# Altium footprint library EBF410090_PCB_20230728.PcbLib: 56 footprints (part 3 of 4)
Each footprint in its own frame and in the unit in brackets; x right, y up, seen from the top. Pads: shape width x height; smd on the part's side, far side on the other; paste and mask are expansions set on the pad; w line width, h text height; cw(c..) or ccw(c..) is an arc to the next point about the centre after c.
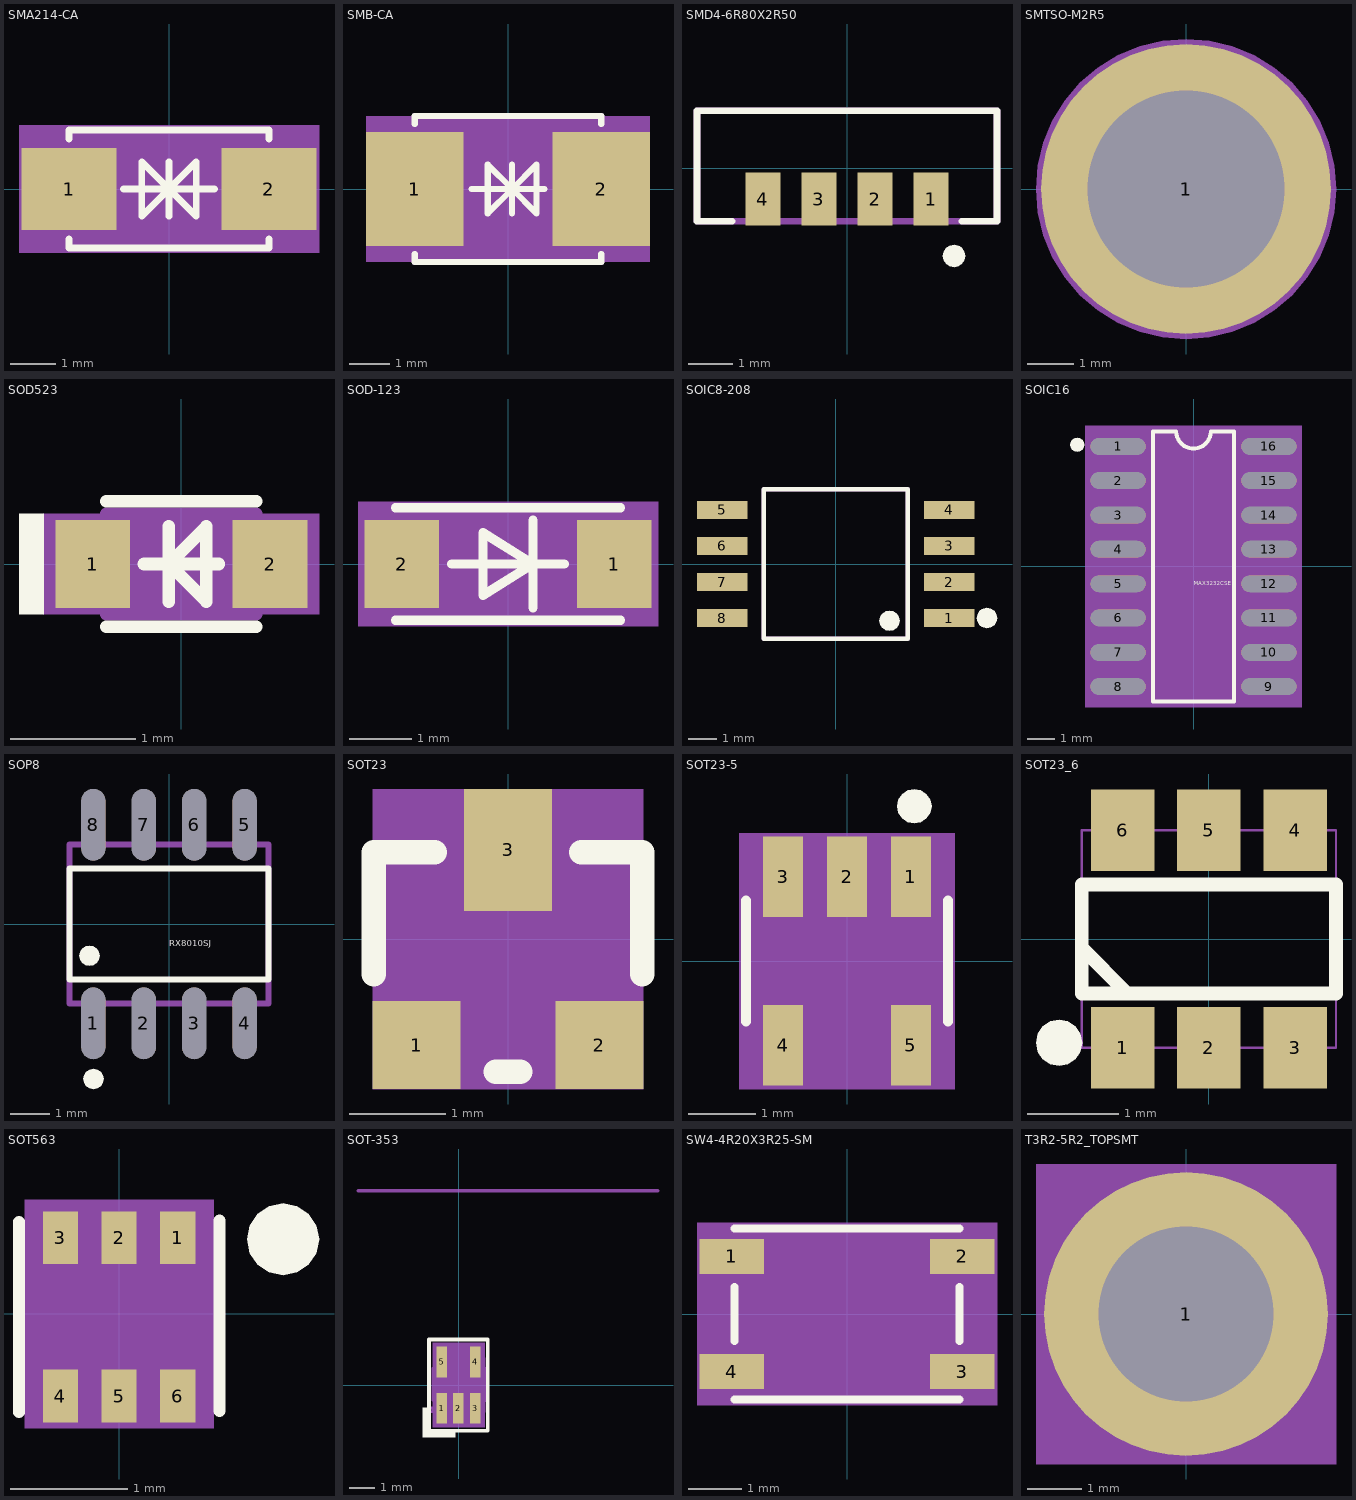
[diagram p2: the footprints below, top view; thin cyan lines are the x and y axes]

## SMA214-CA [mm] "SMA214-CA"
pads (2):
  rect 2.1x1.8 smd: 1(-2.2,0) 2(2.2,0)
Top Overlay:
  lines w0.15: -2.2,-1.1 -2.2,-1.3 2.2,-1.3 2.2,-1.1 ; -2.2,1.1 -2.2,1.3 2.2,1.3 2.2,1.1 ; -1,0 1,0 ; 0,-0.6 0,0.6 ; 0,0 0.6,-0.6 0.6,0.6 0,0 ; 0,0 -0.6,0.6 -0.6,-0.6 0,0
Top 3D Body:
  region: -3.3,1.4 -3.3,-1.4 3.3,-1.4 3.3,1.4
Mechanical 16:
  text "2" at 1.946,0 h0.64
  text "1" at -2.454,0 h0.64
Top Assembly:
  lines w0.15: -2.2,-1.25 -2.2,1.25 2.2,1.25 2.2,-1.25 -2.2,-1.25
3D body: height 3.81, standoff 0, extent -3.3,-1.4 3.3,1.4

## SMB-CA [mm] "SMB-CA"
pads (2):
  rect 2.4x2.8 smd: 1(-2.3,0) 2(2.3,0)
Top Overlay:
  lines w0.15: -2.3,-1.6 -2.3,-1.8 2.3,-1.8 2.3,-1.6 ; -2.3,1.6 -2.3,1.8 2.3,1.8 2.3,1.6 ; -0.9,0 0.9,0 ; 0.1,0 -0.5,0.6 -0.5,-0.6 0.1,0 ; 0.1,0 0.7,-0.6 0.7,0.6 0.1,0 ; 0.1,-0.6 0.1,0.6 0.1,-0.6
Top 3D Body:
  region: -3.5,1.8 -3.5,-1.8 3.5,-1.8 3.5,1.8
Mechanical 16:
  text "2" at 2.3,0.254 h0.64
  text "1" at -2.3,0.254 h0.64
Top Assembly:
  lines w0.15: -2.3,-1.8 -2.3,1.8 2.3,1.8 2.3,-1.8 -2.3,-1.8
3D body: height 3.81, standoff 0, extent -3.5,-1.8 3.5,1.8

## SMD4-6R80X2R50 [mil] "SMD4-6R80X2R50"
pads (4):
  rect 31.5x47.24 smd: 1(75,-27.56) 2(25,-27.56) 3(-25,-27.56) 4(-75,-27.56)
Top Overlay:
  dashed: 85.48,-78.3 86.24,-82.14 88.42,-85.39 91.67,-87.57 95.51,-88.33 99.35,-87.57 100.44,-86.84 102.6,-85.39 104.78,-82.14 105.54,-78.3 104.78,-74.46 102.6,-71.21 100.44,-69.76 99.35,-69.03 95.51,-68.27 91.67,-69.03 88.42,-71.21 86.24,-74.46
  lines w5.91: -102.36,-47.25 -133.86,-47.25 -133.86,51.18 133.86,51.18 133.86,-47.25 102.36,-47.25
Top Assembly:
  lines w5.91: -133.86,-47.25 -133.86,51.18 133.86,51.18 133.86,-47.25 -133.86,-47.25

## SMTSO-M2R5 [mm] "SMTSO-M2R5"
pads (1):
  round 6.2 / inner round 5.2 / far side round 5.2 hole 4.22: 1(0,0)
Top Overlay:
  text "M2.5X3mm" at -0.488,-0.076 h0.15
Top Paste:
  dashed: 3.074,0.4 2.072,0.4 2.029,0.579 1.971,0.754 1.898,0.923 1.81,1.085 1.709,1.238 1.594,1.382 1.468,1.516 1.33,1.638 1.182,1.748 1.025,1.844 0.861,1.927 0.689,1.994 0.513,2.047 0.4,2.072 0.4,3.074 0.666,3.028 0.928,2.958 1.182,2.866 1.427,2.752 1.662,2.617 1.884,2.462 2.091,2.289 2.282,2.098 2.457,1.891 2.612,1.67 2.748,1.436 2.862,1.191 2.955,0.937 3.026,0.675 3.073,0.409
  dashed: 0.4,-3.074 0.4,-2.072 0.579,-2.029 0.754,-1.971 0.923,-1.898 1.085,-1.81 1.238,-1.709 1.382,-1.594 1.516,-1.468 1.638,-1.33 1.748,-1.182 1.844,-1.025 1.927,-0.861 1.994,-0.689 2.047,-0.513 2.072,-0.4 3.074,-0.4 3.028,-0.666 2.958,-0.928 2.866,-1.182 2.752,-1.427 2.617,-1.662 2.462,-1.884 2.289,-2.091 2.098,-2.282 1.891,-2.457 1.67,-2.612 1.436,-2.748 1.191,-2.862 0.937,-2.955 0.675,-3.026 0.409,-3.073
  dashed: -3.074,-0.4 -2.072,-0.4 -2.029,-0.579 -1.971,-0.754 -1.898,-0.923 -1.81,-1.085 -1.709,-1.238 -1.594,-1.382 -1.468,-1.516 -1.33,-1.638 -1.182,-1.748 -1.025,-1.844 -0.861,-1.927 -0.689,-1.994 -0.513,-2.047 -0.4,-2.072 -0.4,-3.074 -0.666,-3.028 -0.928,-2.958 -1.182,-2.866 -1.427,-2.752 -1.662,-2.617 -1.884,-2.462 -2.091,-2.289 -2.282,-2.098 -2.457,-1.891 -2.612,-1.67 -2.748,-1.436 -2.862,-1.191 -2.955,-0.937 -3.026,-0.675 -3.073,-0.409
  dashed: -0.4,3.074 -0.4,2.072 -0.579,2.029 -0.754,1.971 -0.923,1.898 -1.085,1.81 -1.238,1.709 -1.382,1.594 -1.516,1.468 -1.638,1.33 -1.748,1.182 -1.844,1.025 -1.927,0.861 -1.994,0.689 -2.047,0.513 -2.072,0.4 -3.074,0.4 -3.028,0.666 -2.958,0.928 -2.866,1.182 -2.752,1.427 -2.617,1.662 -2.462,1.884 -2.289,2.091 -2.098,2.282 -1.891,2.457 -1.67,2.612 -1.436,2.748 -1.191,2.862 -0.937,2.955 -0.675,3.026 -0.409,3.073
Top 3D Body:
  region: 3.21,0 3.17,0.502 3.053,0.992 2.86,1.457 2.597,1.887 2.27,2.27 1.887,2.597 1.457,2.86 0.992,3.053 0.502,3.17 0,3.21 -0.502,3.17 -0.992,3.053 -1.457,2.86 -1.6,2.772 -1.887,2.597 -2.27,2.27 -2.597,1.887 -2.86,1.457 -3.053,0.992 -3.17,0.502 -3.21,0 -3.17,-0.502 -3.053,-0.992 -2.86,-1.457 -2.597,-1.887 -2.27,-2.27 -1.887,-2.597 -1.6,-2.772 -1.457,-2.86 -0.992,-3.053 -0.502,-3.17 0,-3.21 0.502,-3.17 0.992,-3.053 1.457,-2.86 1.887,-2.597 2.27,-2.27 2.597,-1.887 2.86,-1.457 3.053,-0.992 3.17,-0.502
Mechanical 16:
  text "1" at -0.254,0 h0.64
Top Assembly:
  circle w0.025: c0,0 r3.1
3D body: height 3.81, standoff 0, extent -3.21,-3.21 3.21,3.21

## SOD523 [mm] "SOD523"
pads (2):
  rect 0.6x0.7 smd: 1(-0.71,0) 2(0.71,0)
Top Overlay:
  dashed: -1.3,0.4 -1.3,-0.4 -1.1,-0.4 -1.1,0.4
  lines w0.1: -0.6,-0.5 0.6,-0.5 ; -0.6,0.5 0.6,0.5 ; -0.3,0 0.3,0 ; -0.1,-0.3 -0.1,0.3 ; -0.1,0 0.2,-0.3 0.2,0.3 -0.1,0
Top 3D Body:
  region: -1.1,0.4 -1.1,-0.4 1.1,-0.4 1.1,0.4
Top Assembly:
  lines w0.1: -0.6,-0.4 -0.6,0.4 0.6,0.4 0.6,-0.4 -0.6,-0.4
3D body: height 3.81, standoff 0, extent -1.1,-0.4 1.1,0.4

## SOD-123 [mm] "SOD-123"
pads (2):
  rect 1.2x1.4 smd: 1(1.7,0) 2(-1.7,0)
Top Overlay:
  lines w0.15: -1.8,-0.9 1.8,-0.9 ; -1.8,0.9 1.8,0.9 ; -0.9,0 0.9,0 ; 0.4,-0.7 0.4,0.7 ; -0.4,-0.5 0.4,0 -0.4,0.5 -0.4,-0.5
  text "1N5819W" at 1.199,-0.076 h0.15
Top 3D Body:
  region: -2.4,-1 2.4,-1 2.4,1 -2.4,1
Mechanical 16:
  text "2" at -2.015,0 h0.79
  text "1" at 1.385,0 h0.79
Top Assembly:
  lines w0.15: -1.8,-0.9 -1.8,0.9 1.8,0.9 1.8,-0.9 -1.8,-0.9
3D body: height 3.81, standoff 0, extent -2.4,-1 2.4,1

## SOIC8-208 [mm] "SOIC8-208"
pads (8):
  rect 1.778x0.635 smd: 1(4,-1.905) 2(4,-0.635) 3(4,0.635) 4(4,1.905) 5(-4,1.905) 6(-4,0.635) 7(-4,-0.635) 8(-4,-1.905)
Top Overlay:
  dashed: 2.257,-2 2.23,-2.137 2.152,-2.253 2.037,-2.33 1.9,-2.357 1.763,-2.33 1.724,-2.304 1.647,-2.253 1.57,-2.137 1.543,-2 1.57,-1.863 1.647,-1.747 1.724,-1.696 1.763,-1.67 1.9,-1.643 2.037,-1.67 2.152,-1.747 2.23,-1.863
  dashed: 5.691,-1.905 5.664,-2.042 5.586,-2.157 5.471,-2.235 5.334,-2.262 5.197,-2.235 5.159,-2.209 5.082,-2.157 5.004,-2.042 4.977,-1.905 5.004,-1.768 5.082,-1.653 5.159,-1.601 5.197,-1.575 5.334,-1.548 5.471,-1.575 5.586,-1.653 5.664,-1.768
  lines w0.152: -2.54,-2.64 2.54,-2.64 2.54,2.64 -2.54,2.64 -2.54,-2.64
Top Assembly:
  lines w0.152: -2.54,-2.64 2.54,-2.64 2.54,2.64 -2.54,2.64 -2.54,-2.64

## SOIC16 [mil] "SOIC16"
pads (16):
  oval 80x24 smd: 1(-109.8,174.8) 2(-109.8,125.2) 3(-109.8,74.8) 4(-109.8,25.2) 5(-109.8,-25.2) 6(-109.8,-74.8) 7(-109.8,-125.2) 8(-109.8,-174.8) 9(109.8,-174.8) 10(109.8,-125.2) 11(109.8,-74.8) 12(109.8,-25.2) 13(109.8,25.2) 14(109.8,74.8) 15(109.8,125.2) 16(109.8,174.8)
Top Overlay:
  dashed: -169.29,187.2 -165.45,186.44 -162.2,184.26 -160.02,181.01 -159.26,177.17 -160.02,173.33 -160.75,172.24 -162.2,170.08 -165.45,167.9 -169.29,167.14 -173.13,167.9 -176.38,170.08 -177.83,172.24 -178.56,173.33 -179.32,177.17 -178.56,181.01 -176.38,184.26 -173.13,186.44
  lines w5.91: -59.06,-196.85 59.06,-196.85 59.06,196.85 25.2,196.85 cw(c0,196.85) -25.2,196.85 -39.37,196.85 -59.06,196.85 -59.06,-196.85
  text "MAX3232CSE" at 0.01,-27 h6
Top 3D Body:
  region: -157.48,204.72 -157.48,-204.72 157.48,-204.72 157.48,204.72
Mechanical 16:
  text "8" at -109.8,-179.52 h11.8
  text "13" at 109.8,15.76 h11.8
  text "14" at 109.8,65.36 h11.8
  text "7" at -109.8,-129.92 h11.8
  text "15" at 109.8,115.76 h11.8
  text "16" at 109.8,165.36 h11.8
  text "1" at -109.8,170.08 h11.8
  text "3" at -109.8,70.08 h11.8
  text "12" at 109.8,-34.64 h11.8
  text "9" at 109.8,-179.52 h11.8
  text "10" at 109.8,-134.64 h11.8
  text "4" at -109.8,20.48 h11.8
  text "11" at 109.8,-84.24 h11.8
  text "5" at -109.8,-29.92 h11.8
  text "6" at -109.8,-79.52 h11.8
  text "2" at -109.8,120.48 h11.8
3D body: height 150, standoff 0, extent -157.48,-204.72 157.48,204.72

## SOP8 [mm] "SOP8"
pads (8):
  oval 0.6x1.8 smd: 1(-1.905,-2.5) 2(-0.635,-2.5) 3(0.635,-2.5) 4(1.905,-2.5) 5(1.905,2.5) 6(0.635,2.5) 7(-0.635,2.5) 8(-1.905,2.5)
Top Overlay:
  dashed: -2,-0.545 -1.902,-0.565 -1.82,-0.62 -1.765,-0.703 -1.745,-0.8 -1.765,-0.898 -1.783,-0.925 -1.82,-0.98 -1.902,-1.036 -2,-1.055 -2.098,-1.036 -2.18,-0.98 -2.217,-0.925 -2.235,-0.898 -2.255,-0.8 -2.235,-0.703 -2.18,-0.62 -2.098,-0.565
  dashed: -1.9,-3.645 -1.802,-3.664 -1.72,-3.72 -1.664,-3.802 -1.645,-3.9 -1.664,-3.997 -1.683,-4.025 -1.72,-4.08 -1.802,-4.135 -1.9,-4.155 -1.997,-4.135 -2.08,-4.08 -2.117,-4.025 -2.135,-3.997 -2.155,-3.9 -2.135,-3.802 -2.08,-3.72 -1.997,-3.664
  lines w0.15: -2.5,-1.4 -2.5,1.4 2.5,1.4 2.5,-1.4 -2.5,-1.4
  text "RX8010SJ" at 0,-0.564 h0.15
Mechanical 16:
  text "1" at -1.905,-2.754 h0.64
Top Assembly:
  lines w0.15: -2.5,-2 -2.5,2 2.5,2 2.5,-2 -2.5,-2

## SOT23 [mil] "SOT23"
pads (3):
  rect 36x36 smd: 1(-37.5,-43.5) 2(37.5,-43.5)
  rect 36x50 smd: 3(0,36.5)
Top Overlay:
  lines w10: -55,-14.5 -55,35.5 -30,35.5 ; -5,-54.5 5,-54.5 ; 30,35.5 55,35.5 55,-14.5
Top 3D Body:
  region: -55.5,-61.5 -55.5,61.5 55.5,61.5 55.5,-61.5
3D body: height 150, standoff 0, extent -55.5,-61.5 55.5,61.5

## SOT23-5 [mm] "SOT23-5"
pads (5):
  rect 0.599x1.199 smd: 1(0.95,1.25) 2(0,1.25) 3(-0.95,1.25) 4(-0.95,-1.25) 5(0.95,-1.25)
Top Overlay:
  dashed: 1.255,2.3 1.235,2.202 1.18,2.12 1.098,2.065 1,2.045 0.902,2.065 0.875,2.083 0.82,2.12 0.765,2.202 0.745,2.3 0.765,2.397 0.82,2.48 0.875,2.517 0.902,2.535 1,2.555 1.098,2.535 1.18,2.48 1.235,2.397
  lines w0.15: -1.5,-0.9 -1.5,0.9 ; 1.5,-0.9 1.5,0.9
Top 3D Body:
  region: 1.6,-1.9 1.6,1.9 -1.6,1.9 -1.6,-1.9
Mechanical 16:
  text "5" at 0.91,-1.25 h0.1
  text "3" at -0.99,1.25 h0.1
  text "4" at -0.99,-1.25 h0.1
  text "1" at 0.91,1.25 h0.1
  text "2" at -0.04,1.25 h0.1
Top Assembly:
  lines w0.15: -1.5,-0.85 1.5,-0.85 1.5,0.85 -1.5,0.85 -1.5,-0.85
3D body: height 3.81, standoff 0, extent -1.6,-1.9 1.6,1.9

## SOT23_6 [mm] "SOT23_6"
pads (6):
  rect 0.7x0.9 smd: 1(-0.95,-1.2) 2(0,-1.2) 3(0.95,-1.2) 4(0.95,1.2) 5(0,1.2) 6(-0.95,1.2)
Top Overlay:
  dashed: -1.651,-0.888 -1.553,-0.908 -1.471,-0.963 -1.416,-1.045 -1.396,-1.143 -1.416,-1.241 -1.434,-1.268 -1.471,-1.323 -1.553,-1.378 -1.651,-1.398 -1.749,-1.378 -1.831,-1.323 -1.868,-1.268 -1.886,-1.241 -1.906,-1.143 -1.886,-1.045 -1.831,-0.963 -1.749,-0.908
  lines w0.15: -1.4,-0.1 -0.9,-0.6 ; -1.4,-0.6 1.4,-0.6 1.4,0.6 -1.4,0.6 -1.4,-0.6
Top 3D Body:
  lines w0.025: -1.4,-1.2 1.4,-1.2 1.4,1.2 -1.4,1.2 -1.4,-1.2
Mechanical 16:
  text "3" at 0.95,-1.454 h0.64
  text "5" at 0,0.946 h0.64
  text "4" at 0.95,0.946 h0.64
  text "6" at -0.95,0.946 h0.64
  text "2" at 0,-1.454 h0.64
  text "1" at -0.95,-1.454 h0.64
Top Assembly:
  lines w0.025: -1.4,-1.2 1.4,-1.2 1.4,1.2 -1.4,1.2 -1.4,-1.2

## SOT563 [mm] "SOT563"
pads (6):
  rect 0.3x0.45 smd: 1(0.499,0.65) 2(-0.001,0.65) 3(-0.501,0.65) 4(-0.501,-0.7) 5(-0.001,-0.7) 6(0.499,-0.7)
Top Overlay:
  dashed: 1.703,0.637 1.68,0.519 1.614,0.42 1.514,0.354 1.397,0.331 1.28,0.354 1.247,0.376 1.181,0.42 1.115,0.519 1.091,0.637 1.115,0.754 1.181,0.853 1.247,0.897 1.28,0.919 1.397,0.942 1.514,0.919 1.614,0.853 1.68,0.754
  lines w0.1: -0.854,-0.837 -0.854,0.785 ; 0.854,-0.826 0.854,0.796
Top 3D Body:
  region: 0.804,0.975 -0.804,0.975 -0.804,-0.975 0.804,-0.975
3D body: height 3.81, standoff 0, extent -0.804,-0.975 0.804,0.975

## SOT-353 [mil] "SOT-353"
pads (5):
  rect 16x47 smd: 1(-25.91,-35.43) 2(-0.32,-35.43) 3(25.27,-35.43) 4(25.27,35.43) 5(-25.91,35.43)
Top Overlay:
  dashed: -45.32,-35 -55.32,-35 -55.32,-80 -5.32,-80 -5.32,-70 -45.32,-70
  lines w6: -45.32,-70 -45.32,70 44.68,70 44.68,-70 -45.32,-70
Mechanical 6:
  dashed: -39.69,-65 39.68,-65 39.68,65 -39.69,65
Top 3D Body:
  region: -39.69,-65 39.68,-65 39.68,65 -39.69,65
Mechanical 9:
  circle w1: c-0.32,0 r11.81
  circle w1: c-0.32,0 r11.81
  lines w1: -16.07,0 15.43,0 -16.07,0 ; -0.32,-15.75 -0.32,15.75 -0.32,-15.75
Mechanical 16:
  text "2" at -0.32,-41.83 h16
  text "3" at 25.27,-41.83 h16
  text "1" at -25.91,-41.83 h16
  text "5" at -25.91,29.03 h16
  text "4" at 25.27,29.03 h16
Top Assembly:
  circle w3.94: c-41.32,-38 r2.83
  lines w3.94: -32.32,-24 -32.32,-40.83 -20.32,-40.83 ; -31.5,26 -31.5,40.83 ; -31.5,41.83 -19.5,41.83 -19.5,26 ; -20.32,-40 -20.32,-25 ; -6.32,-24 -6.32,-40.83 5.68,-40.83 ; 5.68,-40 5.68,-24 ; 19.68,-24 19.68,-40.83 31.68,-40.83 ; 19.68,26 19.68,41 ; 19.68,41.83 31.68,41.83 31.68,26 ; 31.68,-40 31.68,-24 ; -39.32,-23.61 -39.32,25.61 40.68,25.61 40.68,-23.61 -39.32,-23.61
Mechanical 19:
  lines w5: -154.32,298 305.68,298
  text "Sofer Lib Information" at -154.32,308 h25
  text "Ref PN: ESDALC6V1W5" at -124.32,258 h25
  text "Creat : Yuki" at -124.32,218 h25
  text "Date  : 2007-11-30" at -124.32,178 h25
  text "Rev   : A1" at -124.32,138 h25
  text "Remark: ***" at -124.32,98 h25
Mechanical 21:
  lines w1: -39.32,-41 40.68,-41 40.68,42 -39.32,42 -39.32,-41
Mechanical 22:
  text "Approved" at -0.32,-112 h35
Mechanical 23:
  text "SOT-353" at 4.68,-247 h30
3D body: height 150, standoff 0, extent -39.69,-65 39.68,65

## SW4-4R20X3R25-SM [mm] "SW4-4R20X3R25-SM"
pads (4):
  rect 1.2x0.65 smd: 1(-2.15,1.075) 2(2.15,1.075) 3(2.15,-1.075) 4(-2.15,-1.075)
Top Overlay:
  lines w0.15: -2.1,-1.6 2.1,-1.6 ; -2.1,-0.5 -2.1,0.5 ; -2.1,1.6 2.1,1.6 ; 2.1,-0.5 2.1,0.5
Top 3D Body:
  region: -2.8,1.7 -2.8,-1.7 2.8,-1.7 2.8,1.7
Top Assembly:
  lines w0.15: -2.1,-1.625 -2.1,1.625 2.1,1.625 2.1,-1.625 -2.1,-1.625
3D body: height 3.81, standoff 0, extent -2.8,-1.7 2.8,1.7

## T3R2-5R2_TOPSMT [mm] "T3R2-5R2_TOPSMT"
pads (1):
  round 5.2 hole 3.2: 1(0,0)
Top Overlay:
  text "M2X3mm" at -0.31,-0.691 h0.15
Top Paste:
  dashed: -0.406,-2.568 -0.629,-2.523 -0.846,-2.458 -1.057,-2.375 -1.26,-2.274 -1.454,-2.156 -1.636,-2.021 -1.806,-1.87 -1.962,-1.706 -2.103,-1.528 -2.228,-1.339 -2.337,-1.14 -2.427,-0.932 -2.499,-0.717 -2.552,-0.496 -2.568,-0.406 -1.548,-0.406 -1.506,-0.54 -1.454,-0.669 -1.39,-0.793 -1.315,-0.911 -1.231,-1.022 -1.137,-1.126 -1.035,-1.221 -0.924,-1.306 -0.807,-1.382 -0.684,-1.447 -0.555,-1.501 -0.422,-1.544 -0.406,-1.548
  dashed: -2.568,0.406 -2.523,0.629 -2.458,0.846 -2.375,1.057 -2.274,1.26 -2.156,1.454 -2.021,1.636 -1.87,1.806 -1.706,1.962 -1.528,2.103 -1.339,2.228 -1.14,2.337 -0.932,2.427 -0.717,2.499 -0.496,2.552 -0.406,2.568 -0.406,1.548 -0.54,1.506 -0.669,1.454 -0.793,1.39 -0.911,1.315 -1.022,1.231 -1.126,1.137 -1.221,1.035 -1.306,0.924 -1.382,0.807 -1.447,0.684 -1.501,0.555 -1.544,0.422 -1.548,0.406
  dashed: 0.406,2.568 0.629,2.523 0.846,2.458 1.057,2.375 1.26,2.274 1.454,2.156 1.636,2.021 1.806,1.87 1.962,1.706 2.103,1.528 2.228,1.339 2.337,1.14 2.427,0.932 2.499,0.717 2.552,0.496 2.568,0.406 1.548,0.406 1.506,0.54 1.454,0.669 1.39,0.793 1.315,0.911 1.231,1.022 1.137,1.126 1.035,1.221 0.924,1.306 0.807,1.382 0.684,1.447 0.555,1.501 0.422,1.544 0.406,1.548
  dashed: 2.568,-0.406 2.523,-0.629 2.458,-0.846 2.375,-1.057 2.274,-1.26 2.156,-1.454 2.021,-1.636 1.87,-1.806 1.706,-1.962 1.528,-2.103 1.339,-2.228 1.14,-2.337 0.932,-2.427 0.717,-2.499 0.496,-2.552 0.406,-2.568 0.406,-1.548 0.54,-1.506 0.669,-1.454 0.793,-1.39 0.911,-1.315 1.022,-1.231 1.126,-1.137 1.221,-1.035 1.306,-0.924 1.382,-0.807 1.447,-0.684 1.501,-0.555 1.544,-0.422 1.548,-0.406
Top 3D Body:
  region: 2.75,2.75 2.75,-2.75 -2.75,-2.75 -2.75,2.75
Mechanical 16:
  text "1" at -0.122,0 h0.3
Top Assembly:
  circle w0.025: c0,0 r2.591
3D body: height 3.81, standoff 0, extent -2.75,-2.75 2.75,2.75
